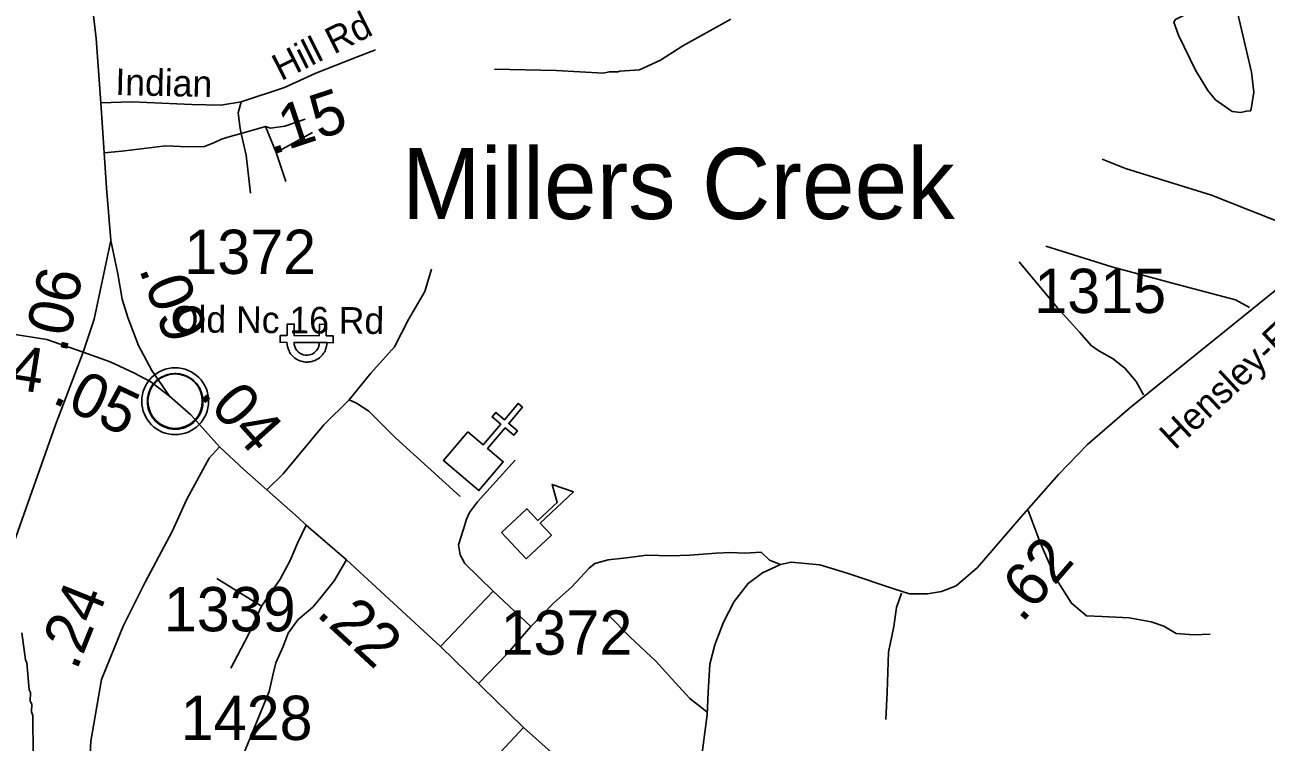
# Model space of a CAD drawing. Extents: x 1248089 to 1457196, y 820910 to 988753.
# Drawn here: x 1339480 to 1342983, y 894091 to 896114 of the extents above; entities that cross this region are included whole.
import ezdxf

# ---------------------------------------------------------------- set-up
doc = ezdxf.new("R2010")
doc.units = 0
for name, color, linetype in [('Exist Civil Demographics Community CELL', 7, 'Continuous'), ('Exist Civil Demographics Community Label', 7, 'Continuous'), ('Exist Cultural Church CELL', 7, 'Continuous'), ('Exist Cultural Educational Facility High CELL', 7, 'Continuous'), ('Exist Hydrographic Misc Water Feature', 7, 'Continuous'), ('Exist Road Non-System Type 51', 7, 'Continuous'), ('Exist Road Primary NC Attributed', 7, 'Continuous'), ('Exist Road Secondary Type 51 Attributed', 7, 'Continuous'), ('Exist Road Secondary Type 51 Label', 7, 'Continuous'), ('Exist Utilities Electrical Power Substation CELL', 7, 'Continuous'), ('Prop CMT Slope Fill', 7, 'Continuous'), ('Prop GRAU CAT1 Cell', 7, 'Continuous'), ('Prop Lane Lines', 7, 'Continuous')]:
    doc.layers.add(name, color=color, linetype=linetype)

msp = doc.modelspace()

# ---------------------------------------------------------------- linework, layer by layer
at = {"layer": 'Exist Civil Demographics Community CELL'}
msp.add_lwpolyline([(1339827.2, 895065.2), (1339828.2, 895070.8), (1339829.9, 895077.3), (1339832.9, 895084.5), (1339835.8, 895090.3), (1339839.1, 895096), (1339842.9, 895101.1), (1339846.9, 895105.5), (1339851.4, 895110.1), (1339857, 895114.7), (1339862.4, 895118.4), (1339867.3, 895121.2), (1339872.3, 895123.7), (1339877.8, 895126), (1339883.4, 895127.8), (1339887.8, 895128.9), (1339892.6, 895129.7), (1339896.7, 895130.4), (1339903.1, 895130.7), (1339907.5, 895130.6), (1339913.2, 895130.3), (1339918.1, 895129.6), (1339923, 895128.6), (1339928, 895127.2), (1339933.2, 895125.2), (1339939.8, 895122.3), (1339946.1, 895118.8), (1339951.2, 895115.3), (1339956.3, 895111.3), (1339959.6, 895108.1), (1339963.8, 895103.7), (1339967.6, 895099), (1339970.7, 895094.5), (1339973.8, 895089.4), (1339976.3, 895084.3), (1339978.3, 895079.3), (1339979.9, 895074.3), (1339981.2, 895069.7), (1339982.3, 895063.6), (1339982.9, 895058.9), (1339983.1, 895052.9), (1339983, 895047.1), (1339982.4, 895041.4), (1339981.4, 895036), (1339979.8, 895029.8), (1339977.9, 895024), (1339975.6, 895018.9), (1339972.5, 895012.9), (1339969.2, 895007.6), (1339965.7, 895002.9), (1339961.5, 894998.1), (1339956.2, 894993.2), (1339951.2, 894989.1), (1339946.2, 894985.6), (1339941.9, 894983.1), (1339935.1, 894979.9), (1339927.9, 894977.2), (1339922, 894975.7), (1339915.4, 894974.4), (1339910.9, 894973.9), (1339906.4, 894973.7), (1339900.9, 894973.7), (1339896.6, 894974.1), (1339890.9, 894974.8), (1339885, 894976.1), (1339880.4, 894977.4), (1339875.3, 894979.3), (1339870.7, 894981.3), (1339866.8, 894983.5), (1339860, 894987.6), (1339854.4, 894991.9), (1339849.5, 894996.4), (1339845, 895001.2), (1339841.8, 895005.2), (1339838.8, 895009.4), (1339834.7, 895016.5), (1339833, 895020), (1339831.3, 895024), (1339828.7, 895032.2), (1339827.2, 895039.3), (1339826.5, 895044.4), (1339826.2, 895050.7), (1339826.1, 895055.4), (1339826.7, 895061.9)], close=True, dxfattribs=at)
for centre, radius in [((1339904.8, 895052.8), 94.3), ((1339904.5, 895053), 76.7)]:
    msp.add_circle(centre, radius, dxfattribs=at)
at = {"layer": 'Exist Cultural Church CELL'}
msp.add_lwpolyline([(1340730.5, 894966.6), (1340774, 894929.9), (1340823.2, 894988), (1340798.7, 895008.7), (1340809.1, 895020.9), (1340833.5, 895000.2), (1340872.3, 895046.2), (1340884.6, 895035.8), (1340845.7, 894989.9), (1340870.2, 894969.2), (1340859.8, 894957), (1340835.4, 894977.7), (1340786.2, 894919.5), (1340830.2, 894882.2), (1340761.5, 894800.9), (1340661.7, 894885.3)], close=True, dxfattribs=at)
at = {"layer": 'Exist Cultural Educational Facility High CELL'}
msp.add_lwpolyline([(1340825, 894682.6), (1340896.4, 894749.6), (1340927.9, 894716), (1340982.7, 894767.4), (1340968.2, 894818.3), (1341028.2, 894796.9), (1340934.5, 894709), (1340966, 894675.4), (1340894.6, 894608.4)], close=True, dxfattribs=at)
at = {"layer": 'Exist Hydrographic Misc Water Feature'}
for points in [[(1342821.5, 896160.9), (1342837.8, 896167), (1342876, 896178.2), (1342886, 896177.9), (1342899.6, 896161.6), (1342941.7, 895980.6), (1342948.4, 895924.4), (1342939.4, 895872), (1342927.2, 895871), (1342911.1, 895867.3), (1342887.2, 895869.9), (1342840, 895903), (1342818.5, 895929.5), (1342783.8, 895986.3), (1342736, 896085.3), (1342722.8, 896121.6), (1342727, 896129.6), (1342753.2, 896142.9), (1342821.5, 896160.9)], [(1340805.7, 895989.4), (1340979.6, 895985.4), (1341113.5, 895978.4), (1341129.6, 895982.1), (1341153.6, 895981.4), (1341159.7, 895983.4), (1341214.8, 895987.4), (1341274.3, 896014.8), (1341337.2, 896055.6), (1341472.9, 896130.2)], [(1339472.2, 894399.3), (1339482.5, 894323.1), (1339486.4, 894315), (1339492.6, 894238.9), (1339496.5, 894230.8), (1339495.9, 894206.8), (1339499.8, 894198.8), (1339499.3, 894176.7), (1339503.1, 894166.7), (1339504.2, 894055.4)]]:
    msp.add_lwpolyline(points, dxfattribs=at)
at = {"layer": 'Exist Road Non-System Type 51'}
msp.add_line((1340164.5, 894804.1), (1340165.4, 894805), dxfattribs=at)
for points in [[(1340091, 895897.5), (1340082.8, 895866.6), (1340087.7, 895822), (1340090.7, 895808.1)], [(1340159.1, 895827.9), (1340173.9, 895822.9), (1340213.6, 895828.9), (1340271, 895848.7)], [(1340090.7, 895808.1), (1340060, 895799.1), (1340035.2, 895792.2), (1340015.4, 895782.3), (1339987.6, 895771.4), (1339940.1, 895770.4), (1339878.6, 895773.4), (1339753.8, 895758.5), (1339704.2, 895753.5)], [(1340090.7, 895808.1), (1340159.1, 895827.9), (1340189.8, 895754.5), (1340216.5, 895672.2)], [(1340090.7, 895808.1), (1340104.6, 895746.6), (1340117.4, 895639.5)], [(1340189.8, 895754.5), (1340291.8, 895811)], [(1343100.7, 895455.3), (1343086.6, 895487.7), (1343051.6, 895528.4), (1343016.5, 895559.8), (1342933.4, 895593), (1342828.2, 895633.6), (1342586.4, 895709.4), (1342520, 895735.2)], [(1342935.7, 895317.3), (1342896.7, 895339), (1342728.7, 895383.3), (1342547.8, 895431.4), (1342361.4, 895490.5)], [(1340395.6, 895056.6), (1340456.5, 895132.3), (1340523, 895206.2), (1340563.4, 895283.2), (1340609.5, 895362.6), (1340628, 895425.4)], [(1342636.4, 895071.2), (1342616.1, 895108.1), (1342584.7, 895145.1), (1342551.5, 895172.8), (1342510.9, 895194.9), (1342488.7, 895209.7), (1342457.4, 895246.7), (1342392.8, 895316.9), (1342285.7, 895446.1)], [(1340165.4, 894805), (1340209.2, 894847.9), (1340323.6, 894986.4), (1340395.6, 895056.6)], [(1340395.6, 895056.6), (1340415.9, 895047.4), (1340451, 895025.2), (1340526.6, 894949.5)], [(1340526.6, 894949.5), (1340708.8, 894783.9)], [(1340801.9, 894517.5), (1340721.7, 894594.9), (1340708.8, 894619.7), (1340703.8, 894647.4), (1340717.7, 894692), (1340726.6, 894719.8), (1340735.5, 894739.3), (1340757.3, 894769.1), (1340864.3, 894886.1)], [(1342311.7, 894745), (1342345, 894654.5), (1342389.3, 894553), (1342433.6, 894482.8), (1342476, 894447.7), (1342520.3, 894445.8), (1342596, 894442.1), (1342658.7, 894431), (1342693.8, 894418.1), (1342728.9, 894397.8), (1342778.7, 894394.1), (1342824.9, 894396)], [(1340148, 894474.7), (1340200.5, 894551.1), (1340229.2, 894603.6), (1340250, 894652.2), (1340273.8, 894702.8)], [(1340760.6, 894256.9), (1340841.8, 894340), (1340908.3, 894417.6), (1340972.9, 894484), (1341022.7, 894528.4), (1341072.5, 894581.9), (1341089.1, 894594.9), (1341126.1, 894605.9), (1341177.7, 894611.5), (1341235, 894618.9), (1341303.2, 894617), (1341356.8, 894618.9)], [(1341356.8, 894618.9), (1341430.6, 894624.4), (1341471.2, 894626.3), (1341511.8, 894624.4), (1341558, 894627.3), (1341582, 894604.1), (1341612.3, 894592.6)], [(1340388.3, 894605.8), (1340353.1, 894546.1), (1340311.5, 894494.5), (1340292.6, 894471.7), (1340251, 894436), (1340223.3, 894398.3), (1340209.4, 894360.7), (1340188.6, 894315), (1340180.7, 894284.3), (1340169.8, 894233.7), (1340093.3, 894047.5)], [(1340022.1, 894553), (1340148, 894474.7)], [(1340653.6, 894360.8), (1340801.9, 894517.5)], [(1340801.9, 894517.5), (1340908.3, 894417.6)], [(1341954.4, 894511.5), (1341939.7, 894470.8), (1341932.3, 894417.3), (1341917.5, 894345.2), (1341913.8, 894232.6), (1341910.1, 894155)], [(1340148, 894474.7), (1340109.3, 894391.4), (1340061.7, 894300.2)], [(1341404.5, 894176.5), (1341357, 894214.3), (1341314.5, 894260.5), (1341261, 894319.6), (1341187.2, 894387.9), (1341126.3, 894450.7)]]:
    msp.add_lwpolyline(points, dxfattribs=at)
at = {"layer": 'Exist Road Primary NC Attributed'}
for points in [[(1339694.4, 895894.4), (1339681.5, 896076), (1339631.4, 896500.9), (1339622.8, 896595.8), (1339612.4, 896692.6), (1339591.6, 896921.1), (1339577.8, 897040.5), (1339567.4, 897087.3), (1339513.8, 897305.4), (1339471.5, 897484)], [(1339723, 895505.8), (1339710.9, 895655.1), (1339704.2, 895753.5), (1339694.4, 895894.4)], [(1339645, 895191), (1339676.3, 895284.6), (1339723, 895505.8)], [(1338877.1, 892788.3), (1338953.6, 893196.7), (1339024.9, 893441.4), (1339128.4, 893771.4), (1339297.6, 894251.5), (1339339.1, 894352.7), (1339454.9, 894669.4), (1339567.4, 894986.2), (1339645, 895191)]]:
    msp.add_lwpolyline(points, dxfattribs=at)
at = {"layer": 'Exist Road Secondary Type 51 Attributed'}
for points in [[(1339694.4, 895894.4), (1339782.7, 895897.5), (1339951.6, 895889.8), (1340033.7, 895888.2), (1340091, 895897.5), (1340213.4, 895937.8), (1340301.7, 895978.1), (1340416.3, 896023.1), (1340470.2, 896044.2)], [(1339723, 895505.8), (1339743, 895411.7), (1339755.1, 895340.4), (1339771.3, 895289.3), (1339800.8, 895209.9), (1339838.5, 895139.9), (1339888.2, 895067.3)], [(1343110.9, 895447.9), (1342943.5, 895312.8), (1342597.2, 895033.3), (1342478.8, 894931), (1342397, 894845.9), (1342291.9, 894727.1), (1342168.1, 894583.8), (1342108.5, 894532.3), (1342066.5, 894516.1), (1342027.8, 894509.7), (1341976.1, 894509.7), (1341932, 894523.7), (1341800.7, 894567.8), (1341723.2, 894591.5), (1341642.5, 894599), (1341612.3, 894592.6), (1341561.8, 894568.9), (1341520.9, 894538.7), (1341482.1, 894488.1), (1341452, 894430), (1341427.2, 894365.3), (1341413.2, 894311.5), (1341408.9, 894231.8), (1341405.5, 894168), (1341369.9, 893897.4)], [(1339423.3, 895245.5), (1339542.9, 895226.7), (1339645, 895191)], [(1339645, 895191), (1339721.6, 895164.1), (1339787.5, 895133.1), (1339835.9, 895107.6), (1339888.2, 895067.3)], [(1339888.2, 895067.3), (1339948.8, 895014.7), (1340029.4, 894924.6)], [(1340029.4, 894924.6), (1340000.9, 894891.8), (1339937.7, 894776.1), (1339896.2, 894685.5), (1339819.5, 894542.3), (1339757.6, 894418.6), (1339697.2, 894267.9), (1339666.5, 894093.8), (1339664.6, 894057.5), (1339661.5, 894005.6), (1339664.6, 893958.3), (1339681.4, 893862.2), (1339707.3, 893756.8)], [(1340029.4, 894924.6), (1340098, 894860), (1340252.6, 894724.2), (1340273.8, 894702.8), (1340388.3, 894605.8), (1340653.6, 894360.8), (1340887.4, 894132.6)], [(1340887.4, 894132.6), (1340772.5, 894009.2), (1340652.7, 893879.6), (1340560.4, 893775.8), (1340477.8, 893690), (1340416.8, 893623.9)], [(1340887.4, 894132.6), (1341051.3, 893986.6), (1341090.2, 893949.3), (1341255.4, 893803.4), (1341319.6, 893746.1)]]:
    msp.add_lwpolyline(points, dxfattribs=at)
at = {"layer": 'Exist Utilities Electrical Power Substation CELL'}
msp.add_lwpolyline([(1340201, 895238.3), (1340220.5, 895238.2), (1340220.7, 895270.4), (1340240.5, 895270.2), (1340240.3, 895238), (1340311.2, 895237.5), (1340311.4, 895269.7), (1340331.2, 895269.6), (1340331, 895237.4), (1340350.5, 895237.2), (1340350.4, 895217.8), (1340330.8, 895218), (1340311, 895218.1), (1340240.2, 895218.6), (1340240.8, 895212.4), (1340242, 895207.1), (1340244.3, 895201.5), (1340248, 895196), (1340252.6, 895191.2), (1340255.2, 895189.2), (1340258.3, 895187.5), (1340262.1, 895185.4), (1340266.2, 895184), (1340271, 895183), (1340274.6, 895182.7), (1340278.8, 895182.9), (1340283.6, 895183.5), (1340287.8, 895184.7), (1340290.8, 895185.9), (1340294.1, 895187.7), (1340297.5, 895190), (1340300.7, 895192.8), (1340303.4, 895195.8), (1340305.6, 895198.6), (1340306.9, 895201), (1340308.4, 895203.7), (1340309.7, 895207.3), (1340310.2, 895209.5), (1340311.1, 895213.2), (1340311.3, 895216), (1340311.5, 895218.1), (1340333.1, 895218), (1340332.7, 895214.5), (1340332.3, 895211.8), (1340331.8, 895208.5), (1340331, 895205.2), (1340329.9, 895201.4), (1340328.8, 895198.3), (1340327.5, 895195.1), (1340325.7, 895191.6), (1340323.4, 895188.1), (1340320.8, 895184.5), (1340318.2, 895181.5), (1340315.5, 895178.7), (1340311.9, 895175.6), (1340308.1, 895172.7), (1340303.8, 895170.2), (1340299.4, 895168), (1340296.1, 895166.6), (1340292.9, 895165.6), (1340289.8, 895164.8), (1340286, 895164), (1340282.2, 895163.5), (1340278.8, 895163.2), (1340274.4, 895163.2), (1340271.4, 895163.4), (1340268, 895163.9), (1340264.4, 895164.6), (1340259.6, 895165.8), (1340254.6, 895167.7), (1340250.2, 895169.7), (1340246.6, 895171.8), (1340242.4, 895174.6), (1340239.3, 895177.3), (1340237.4, 895178.9), (1340235, 895181.4), (1340233.1, 895183.6), (1340230.3, 895186.9), (1340227.6, 895191.2), (1340225.8, 895194.9), (1340224.2, 895198.3), (1340223.1, 895201.5), (1340221.5, 895206.7), (1340220.7, 895211), (1340220.3, 895214.8), (1340220.1, 895218.7), (1340200.8, 895218.9)], close=True, dxfattribs=at)

# ---------------------------------------------------------------- texts
at = {"layer": 'Exist Civil Demographics Community Label'}
msp.add_text('Millers Creek', height=200, dxfattribs=at).set_placement((1340544, 895566.8))
at = {"layer": 'Exist Road Secondary Type 51 Label'}
for s, rotation, p in [('Hill Rd', 26.7185, (1340203.3, 895955.1)), ('Indian', 358.7592, (1339735.2, 895916.5)), ('Hensley-Eller Rd', 42.9384, (1342725.5, 894913.2)), ('Old Nc 16 Rd', 359.5658, (1339892.2, 895247))]:
    msp.add_text(s, height=75, rotation=rotation, dxfattribs=at).set_placement(p)
at = {"layer": 'Prop CMT Slope Fill'}
msp.add_text('.06', height=125, rotation=78.0781, dxfattribs=at).set_placement((1339597.2, 895185.9))
at = {"layer": 'Prop GRAU CAT1 Cell'}
for s, rotation, p in [('.15', 18.2307, (1340177.6, 895747.1)), ('.09', 290.4345, (1339801.4, 895426)), ('.04', 351.0538, (1339295.2, 895111.2)), ('.05', 334.8378, (1339553.3, 895050.7)), ('.04', 311.8229, (1339968.8, 895070.5)), ('.62', 49.1737, (1342293.7, 894425.1)), ('.24', 68.1259, (1339626.5, 894290.8)), ('.22', 317.2843, (1340299.5, 894450.7))]:
    msp.add_text(s, height=125, rotation=rotation, dxfattribs=at).set_placement(p)
at = {"layer": 'Prop Lane Lines'}
for s, p in [('1372', (1339930.4, 895411.6)), ('1315', (1342328.7, 895301.5)), ('1339', (1339872.6, 894403.8)), ('1372', (1340822.6, 894337.8)), ('1428', (1339920.3, 894097.2))]:
    msp.add_text(s, height=125, dxfattribs=at).set_placement(p)

doc.saveas('drawing.dxf')
